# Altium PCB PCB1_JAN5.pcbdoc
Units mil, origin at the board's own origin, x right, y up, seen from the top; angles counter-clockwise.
Board outline 1410 x 855 mil, 2 copper layers (Top Layer, Bottom Layer); 71 components, 53 nets, 261 pads, 16 vias.
Unrouted connection lines stored in the file: 119.
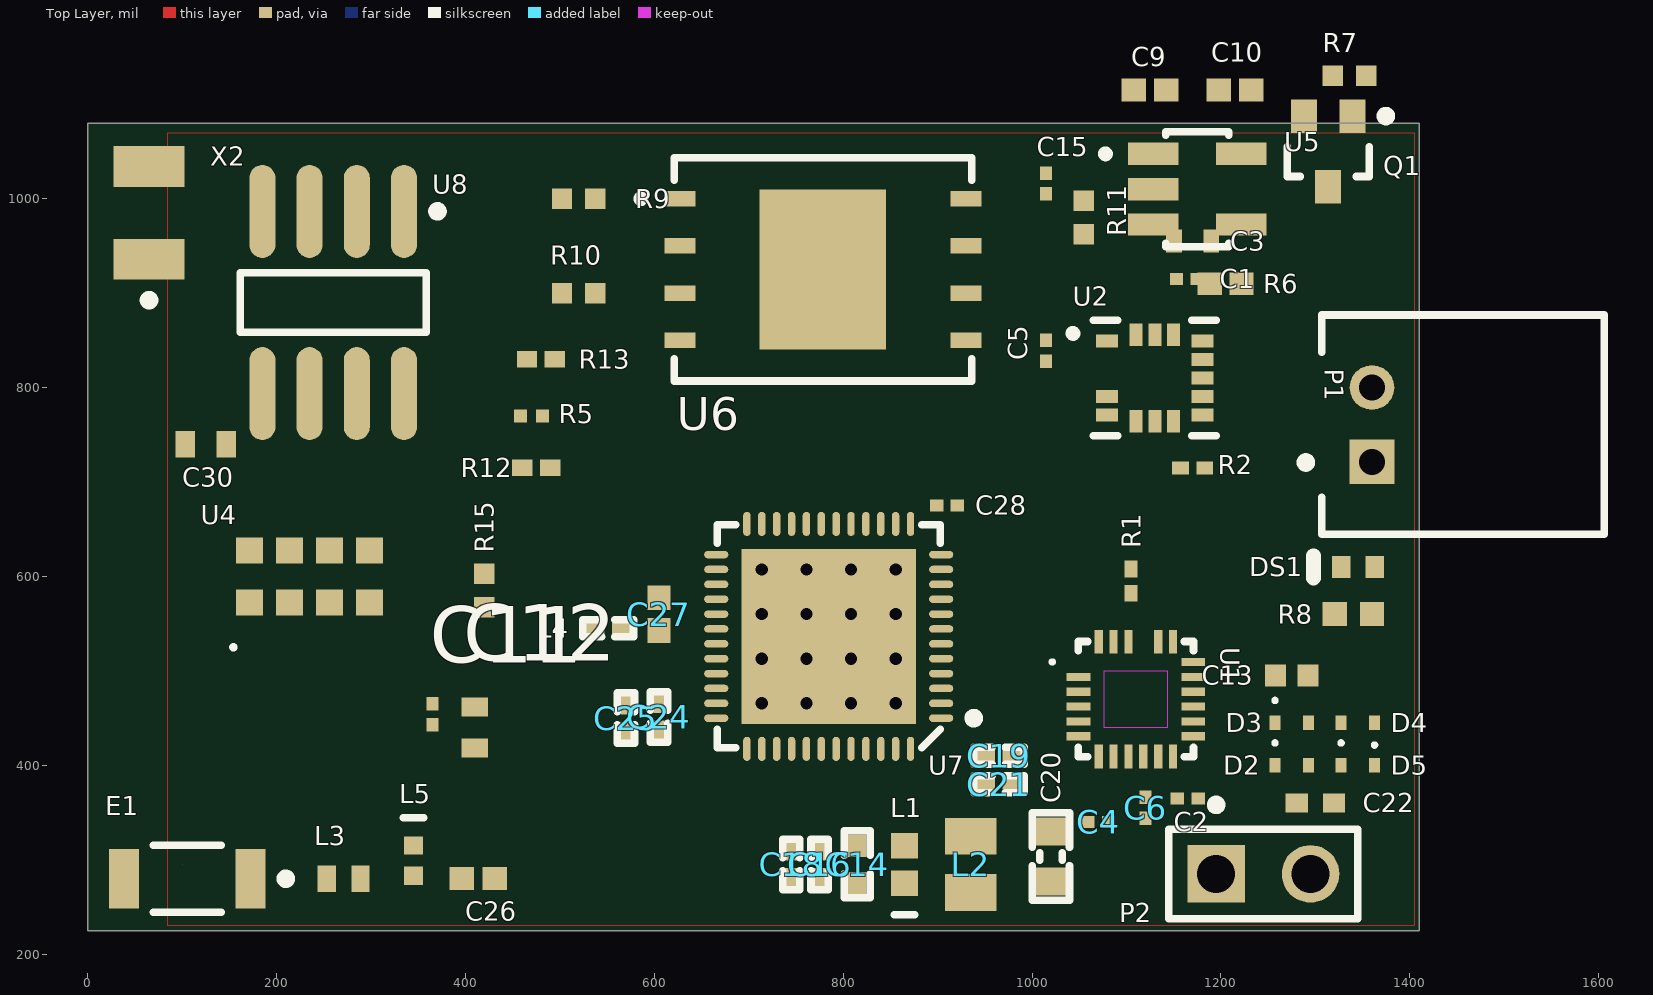
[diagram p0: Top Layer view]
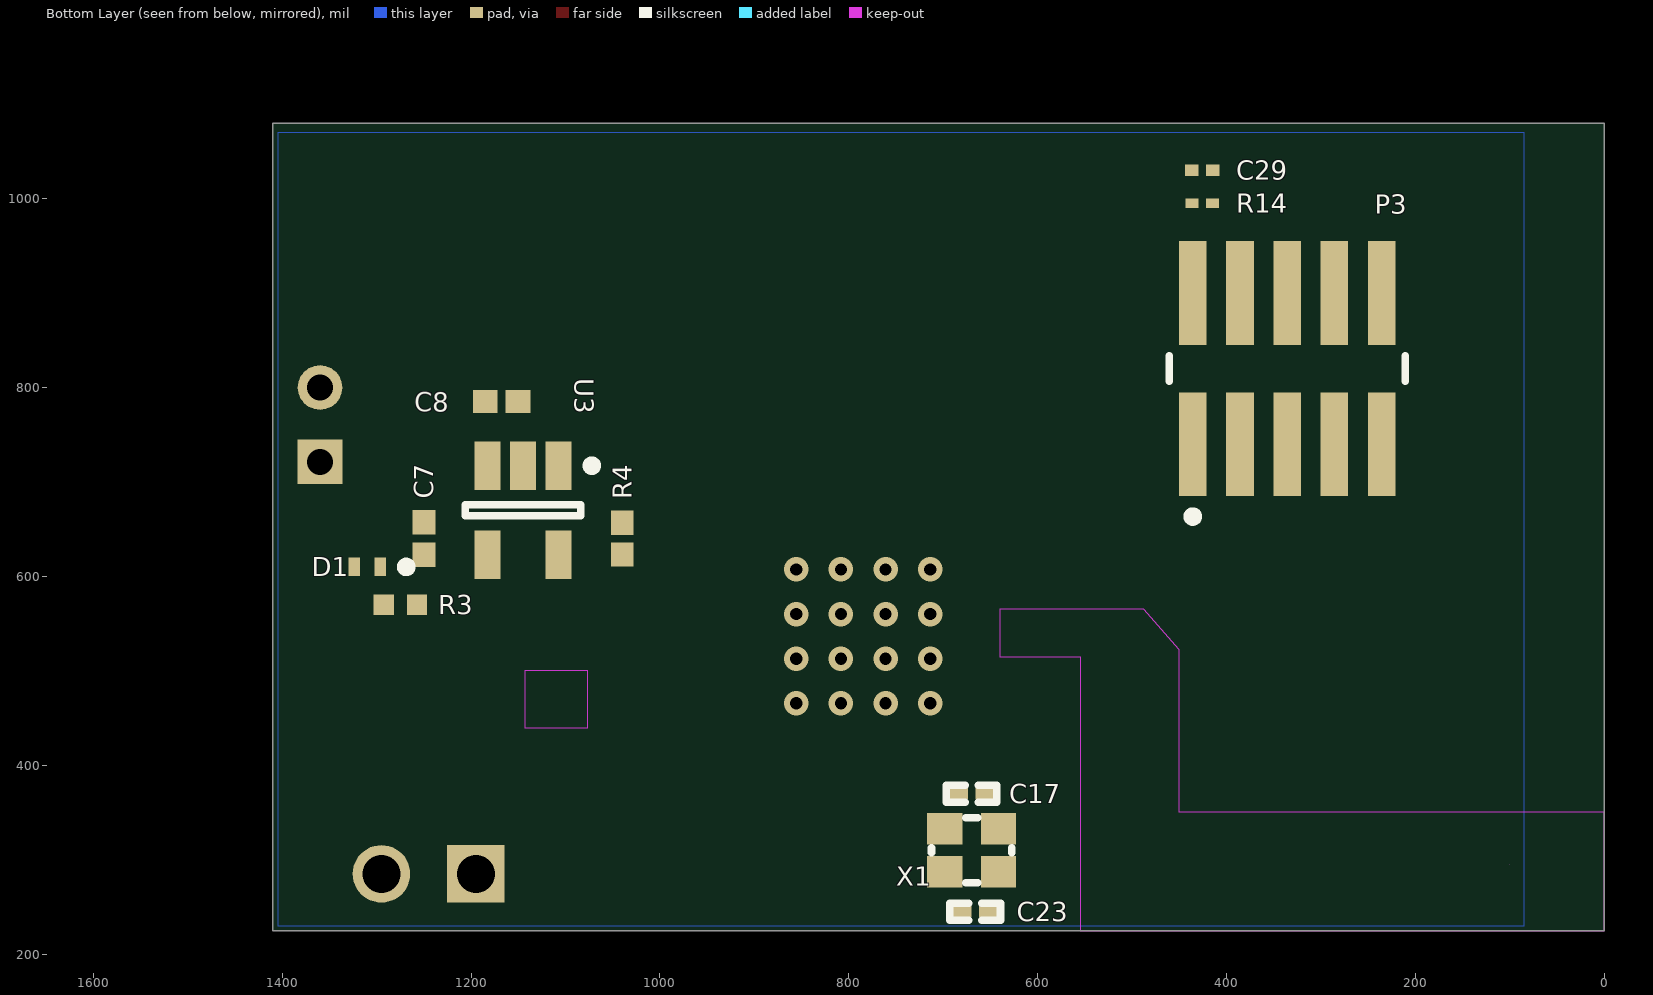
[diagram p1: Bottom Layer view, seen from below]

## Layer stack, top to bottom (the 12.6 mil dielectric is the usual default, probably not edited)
Top Solder: solder mask 0.4, Solder Resist, Dk 3.5
Top Layer: signal copper 1.4
Dielectric 1: dielectric 12.6, FR-4, Dk 4.8
Bottom Layer: signal copper 1.4
Bottom Solder: solder mask 0.4, Solder Resist, Dk 3.5

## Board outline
1410,225 1410,1080 0,1080 0,225
cut-out: 100,295

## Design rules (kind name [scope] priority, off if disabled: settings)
Clearance CPWG [InNet('RF')] p1: gap=5 ignorepadtopadclearanceinfootprint=TRUE // RF
Clearance [All] p2: gap=5 ignorepadtopadclearanceinfootprint=TRUE except(10: Via-Via)
HoleSize [All] p1: absolutevalues=TRUE maxlimit=100 minlimit=0.6 maxpercent=80.000 minpercent=20.000
MinimumSolderMaskSliver [All] p1: minsoldermaskwidth=5
PolygonConnect PolygonConnect_5 [All vs IsNamedPolygon('Top Layer-GND')] p1: thpad.connectstyle=Relief thpad.reliefconductorwidth=10 thpad.reliefentries=4 thpad.polygonreliefangle="90 Angle" thpad.airgapwidth=10 smdpad.connectstyle=Direct smdpad.reliefconductorwidth=10 smdpad.reliefentries=4 smdpad.polygonreliefangle="90 Angle" smdpad.airgapwidth=10 via.connectstyle=Direct via.reliefconductorwidth=10 via.reliefentries=4 via.polygonreliefangle="90 Angle" via.airgapwidth=10
PolygonConnect PolygonConnect_4 [All vs IsNamedPolygon('Bottom Layer-GND')] p2: thpad.connectstyle=Relief thpad.reliefconductorwidth=10 thpad.reliefentries=4 thpad.polygonreliefangle="90 Angle" thpad.airgapwidth=10 smdpad.connectstyle=Direct smdpad.reliefconductorwidth=10 smdpad.reliefentries=4 smdpad.polygonreliefangle="90 Angle" smdpad.airgapwidth=10 via.connectstyle=Direct via.reliefconductorwidth=10 via.reliefentries=4 via.polygonreliefangle="90 Angle" via.airgapwidth=10
PolygonConnect PolygonConnect_3 [All vs IsNamedPolygon('Top Layer-GND')] p3: thpad.connectstyle=Relief thpad.reliefconductorwidth=10 thpad.reliefentries=4 thpad.polygonreliefangle="90 Angle" thpad.airgapwidth=10 smdpad.connectstyle=Relief smdpad.reliefconductorwidth=10 smdpad.reliefentries=4 smdpad.polygonreliefangle="90 Angle" smdpad.airgapwidth=10 via.connectstyle=Direct via.reliefconductorwidth=10 via.reliefentries=4 via.polygonreliefangle="90 Angle" via.airgapwidth=10
PolygonConnect PolygonConnect_2 [All vs IsNamedPolygon('Bottom Layer-GND')] p4: thpad.connectstyle=Relief thpad.reliefconductorwidth=10 thpad.reliefentries=4 thpad.polygonreliefangle="90 Angle" thpad.airgapwidth=10 smdpad.connectstyle=Direct smdpad.reliefconductorwidth=10 smdpad.reliefentries=4 smdpad.polygonreliefangle="90 Angle" smdpad.airgapwidth=10 via.connectstyle=Relief via.reliefconductorwidth=10 via.reliefentries=4 via.polygonreliefangle="90 Angle" via.airgapwidth=10
PolygonConnect PolygonConnect_1 [All vs IsNamedPolygon('Top Layer-GND')] p5: thpad.connectstyle=Relief thpad.reliefconductorwidth=10 thpad.reliefentries=4 thpad.polygonreliefangle="90 Angle" thpad.airgapwidth=10 smdpad.connectstyle=Direct smdpad.reliefconductorwidth=10 smdpad.reliefentries=4 smdpad.polygonreliefangle="90 Angle" smdpad.airgapwidth=10 via.connectstyle=Relief via.reliefconductorwidth=10 via.reliefentries=4 via.polygonreliefangle="90 Angle" via.airgapwidth=10
PolygonConnect [All] p6: connectstyle=Relief reliefconductorwidth=10 reliefentries=4 polygonreliefangle="90 Angle" airgapwidth=10
RoutingVias [All] p1: holewidth=12 width=24 viastyle="Through Hole" minholewidth=12 minwidth=24 maxholewidth=12 maxwidth=24
SilkToSilkClearance [All] p1: silktosilkclearance=7
SilkToSolderMaskClearance [IsPad] p1: minsilkscreentomaskgap=5 clearancetoexposedcopper=TRUE
SolderMaskExpansion [All] p1: expansion=4
Width RF2 [InNet('NetE1_1')] p1: maxlimit=35 minlimit=35 preferedwidth=35 minimp=50.000000 maximp=50.000000 favimp=50.000000
Width RF1 [InNet('NetC26_1')] p2: maxlimit=35 minlimit=35 preferedwidth=35 minimp=50.000000 maximp=50.000000 favimp=50.000000
Width RF [InNet('RF')] p3: maxlimit=35 minlimit=35 preferedwidth=35 minimp=50.000000 maximp=50.000000 favimp=50.000000
Width [All] p4: maxlimit=8 minlimit=8 preferedwidth=8 minimp=50.000000 maximp=50.000000 favimp=50.000000
26 further rules are at their usual default settings.

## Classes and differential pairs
component class "SimPL_IMU_v1_1 _JAN5": C14 C15 C16 C17 C18 C19 C20 C21 C23 C24 C25 C26 C27 C28 C29 C30 E1 L1 L2 L3 L4 L5 P3 R9 R10 R11 R12 R13 R14 R15 U6 U7 U8 X1 X2
component class SimPL_IMU_v1_0_JAN5: C1 C2 C3 C4 C5 C6 C7 C8 C9 C10 C11 C12 C13 C22 D1 D2 D3 D4 D5 DS1 P1 P2 Q1 R1 R2 R3 R4 R5 R6 R7 R8 U1 U2 U3 U4 U5

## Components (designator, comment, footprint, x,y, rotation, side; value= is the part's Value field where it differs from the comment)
C1 "0.1uF" CAPC0603X33X15LL03T05 1163.98,915 r180 top
C2 "0.1uF" CAPC0603X33X15LL03T05 1165,365 r0 top
C3 "1.0uF" CAPC1005X70X10LL20T00 1170,955 r180 top
C4 "0.1uF" CAPC0603X33X15LL03T05 1070,340 r0 top
C5 "0.1uF" CAPC0603X33X15LL03T05 1015,838.98 r90 top
C6 "0.1uF" CAPC0603X33X15LL03T05 1120,355 r90 top
C7 "4.7uF" CAPC1005X55X25NL05T10 1250,640 r270 bottom
C8 "4.7uF" CAPC1005X55X25NL05T10 1167.68,785 r0 bottom
C9 "1uF" CAPC1005X55X25NL05T10 1125,1115 r0 top
C10 "1uF" CAPC1005X55X25NL05T10 1215,1115 r0 top
C11 "0.1uF" CAPC0603X33X15LL03T05 365,453.98 r90 top
C12 "TACK225M006QTA" CAPC1005X70X10NL20T00 410,440 r90 top
C13 "CL05A226MQ5QUNC" *CAPC1005X55N 1275,495 r180 top
C14 "1.0µF" CAPC1005X04L 815,295 r90 top
C15 "0.1uF" CAPC0603X33X15LL03T05 1015,1016.02 r270 top
C16 "12pF" CAPC0603X03L 775,295 r90 top
C17 "12pF" CAPC0603X03L 670,370 r180 bottom
C18 "12pF" CAPC0603X03L 745,295 r90 top
C19 "100nF" CAPC0603X03L 965,410 r0 top
C20 "4.7µF" CAPC1608X06L 1020,303.43 r270 top
C21 "100nF" CAPC0603X03L 965,380 r0 top
C22 "6.8nF" 0402 1300,360 r180 top
C23 "12pF" CAPC0603X03L 666.22,245 r0 bottom
C24 "100pF" CAPC0603X03L 605,451.22 r270 top
C25 "100pF" CAPC0603X03L 570,450 r90 top
C26 "1.0pF" CAPC1005X55X25NL05T10 413.58,279.96 r0 top
C27 "1.0pF" CAPC1005X55X25NL05T10 605,560 r270 top
C28 "0.1uF" CAPC0603X33X15LL03T05 910,675 r180 top
C29 "02016D104KAT2A" CAPC0603X33X15LL03T05 425.83,1030 r180 bottom
C30 "TACK225M006QTA" CAPC1005X70X10NL20T00 125,740 r0 top
D1 "LNJ247W82RA" PNSC-CHIP-2_V 1310,610 r180 bottom
D2 "NSR0140P2T5G" ONSC-SOD-923-2-514AA-01_D_V 1275,400 r0 top
D3 "NSR0140P2T5G" ONSC-SOD-923-2-514AA-01_D_V 1275,445 r0 top
D4 "NSR0140P2T5G" ONSC-SOD-923-2-514AA-01_D_V 1345,445 r180 top
D5 "NSR0140P2T5G" ONSC-SOD-923-2-514AA-01_D_V 1345,400 r0 top
DS1 "SML-P11MTT86" ROHM-SML-P11MT_V 1345.24,610 r180 top
E1 "2450AT18A100E" JT-2450AT18A100-2_V 105.51,279.81 r180 top
L1 "15nH" INDC1005X55X25ML05T10_A 865,295 r90 top
L2 "10uH" MURA-IND0805_L 935,295 r270 top
L3 "3.9nH" *INDC1006X60N 271.09,279.81 r180 top
L4 "3.3nH" INDC0603X03L 551.22,545 r180 top
L5 "2.7nH" INDC1005X55X25LL05T10_A 345,299.06 r270 top
P1 "Battery Header" JST-S2B-PH-K-S_V 1456.46,760.63 r90 top
P2 "2pin header" AMPH-68000-102HLF_V 1245,285 r0 top
P3 "FTSH-105-01-L-DV-K-TR" SMTC-FTSH-105-01-L-DV-K_V 335.83,820 r180 bottom
Q1 "BSS138W-7-F" DIOD-SOT323-3_V 1313.62,1050 r270 top
R1 "10k" RESC0603X26X15NL03T05 1105,595 r90 top
R2 "10k" RESC0603X26X15NL03T05 1170,715 r0 top
R3 "330" RESC1005X40X25NL05T05 1275,570 r180 bottom
R4 "2.2K" RESC1005X40X25NL10T10 1040,640 r270 bottom
R5 "8.2k" RESC0201(0603)_L 470,770 r0 top value="8200.00 Ohm"
R6 "2.2k" RESC1005X40X25NL10T10 1205,910 r0 top
R7 "CRCW04022K20FKED" RESC1005X40X25NL05T05 1336.34,1130 r0 top
R8 "ERJ2RKF3300X" RESC1005X40X25ML05T05 1340.32,560 r180 top
R9 "10k" RESC1005X40X25NL05T05 520,1000 r180 top
R10 "10k" RESC1005X40X25NL05T05 520,900 r180 top
R11 "10k" RESC1005X40X25NL05T05 1055,980 r90 top
R12 "2.2K" RESC0603X28X15ML05T05 475,715 r0 top
R13 "2.2K" RESC0603X28X15ML05T05 480,830 r0 top
R14 "ERJ-1GEJ104C" RESC0603X26X15LL03T05 425.83,995 r0 bottom
R15 "1k" RESC1005X40X25NL05T05 420,585 r90 top
U1 "ICM-20649" *QFN40P300X300X95-24N 1110,470 r0 top
U2 "ADXL372BCCZ-RL7" *PQFN50P322X300X114-16N 1130,810 r0 top
U3 "MCP73831T-2ATI/OT" SOT-23-OT5_M 1145,670 r270 bottom
U4 "VCNL4040M3OE" *VISHAY_VCNL4040_4X2X1.1 235,600 r90 top
U5 "AP2112K-3.3TRG1" *SOT95P285X140-5N 1175,1010 r0 top
U6 "MT25QL256ABA1EW9-0SIT" *SON127P600X800X80-9N 778.62,925 r0 top
U7 "nRF52832-QFAA" QFN40P600X600X90-48N 784.73,536.46 r180 top
U8 "DS1388Z-33+T&R" S8+4_M 260,890 r270 top
X1 "32MHz" BT-XTAL_2016 670,310 r180 bottom
X2 "32.768KHz-T" ABRA-ABS07-2_V 65,985 r90 top

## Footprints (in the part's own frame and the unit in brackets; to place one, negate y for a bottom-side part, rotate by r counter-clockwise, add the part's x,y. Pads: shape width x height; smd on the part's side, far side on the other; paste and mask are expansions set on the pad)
0402 [mm] "Chip Capacitor, Body 1.0x0.5mm, IPC High Density"
  rect 0.6x0.5 smd: 1(-0.5,0) 2(0.5,0)
  body extent -0.55,-0.3 0.55,0.3, height 1.3
*CAPC1005X55N [mm]
  rect 0.56x0.6 smd: 1(-0.435,0) 2(0.435,0)
*INDC1006X60N [mm]
  rect 0.49x0.7 smd: 1(-0.453,0) 2(0.453,0)
*PQFN50P322X300X114-16N [mm]
  rect 0.6x0.35 smd: 1(-1.285,1) 4(-1.285,-0.5) 5(-1.285,-1) 9(1.285,-1) 10(1.285,-0.5) 11(1.285,0) 12(1.285,0.5) 13(1.285,1)
  rect 0.6x0.35 on Top Overlay: 2(-1.285,0.5) 3(-1.285,0)
  rect 0.35x0.6 smd: 6(-0.5,-1.165) 7(0,-1.165) 8(0.5,-1.165) 14(0.5,1.165) 15(0,1.165) 16(-0.5,1.165)
  silkscreen extent -2.3,-1.55 1.65,1.55
*QFN40P300X300X95-24N [mm]
  rect 0.64x0.22 on Top Overlay: 1(-1.545,1)
  rect 0.64x0.22 smd: 2(-1.545,0.6) 3(-1.545,0.2) 4(-1.545,-0.2) 5(-1.545,-0.6) 6(-1.545,-1) 13(1.545,-1) 14(1.545,-0.6) 15(1.545,-0.2) 16(1.545,0.2) 17(1.545,0.6) 18(1.545,1)
  rect 0.22x0.64 smd: 7(-1,-1.545) 8(-0.6,-1.545) 9(-0.2,-1.545) 10(0.2,-1.545) 11(0.6,-1.545) 12(1,-1.545) 19(1,1.545) 20(0.6,1.545) 22(-0.2,1.545) 23(-0.6,1.545) 24(-1,1.545)
  rect 0.22x0.64 on Top Overlay: 21(0.2,1.545)
  Keep-Out Layer region: -0.85,0.77 0.85,0.77 0.85,-0.77 -0.85,-0.77
  Keep-Out Layer region: -0.85,0.77 0.85,0.77 0.85,-0.77 -0.85,-0.77
  Keep-Out Layer region: -0.85,0.77 0.85,0.77 0.85,-0.77 -0.85,-0.77
  Keep-Out Layer region: -0.85,0.77 0.85,0.77 0.85,-0.77 -0.85,-0.77
  Keep-Out Layer region: -0.85,0.77 0.85,0.77 0.85,-0.77 -0.85,-0.77
  Keep-Out Layer region: -0.85,0.77 0.85,0.77 0.85,-0.77 -0.85,-0.77
  silkscreen extent -2.3,-1.55 1.55,1.55
*SON127P600X800X80-9N [mm]
  rect 0.84x0.42 smd: 1(-3.845,1.905) 2(-3.845,0.635) 3(-3.845,-0.635) 4(-3.845,-1.905) 5(3.845,-1.905) 6(3.845,-0.635) 7(3.845,0.635) 8(3.845,1.905)
  rect 3.4x4.3 smd: 9(0,0)
  silkscreen extent -4.99,-3 4,3
*SOT95P285X140-5N [mm]
  rect 1.35x0.6 smd: 1(-1.185,0.95) 2(-1.185,0) 3(-1.185,-0.95) 4(1.185,-0.95) 5(1.185,0.95)
  silkscreen extent -2.57,-1.55 0.85,1.55
*VISHAY_VCNL4040_4X2X1.1 [mm]
  rect 0.7x0.725 smd: 1(-0.7,1.612) 2(-0.7,0.538) 3(-0.7,-0.537) 4(-0.7,-1.612) 5(0.7,-1.612) 6(0.7,-0.537) 7(0.7,0.538) 8(0.7,1.612)
  silkscreen extent -1.96,2 -1.86,2.1
ABRA-ABS07-2_V [mm] "Hand Drawn, 2-Leads, Body 3.2x1.5mm, Pitch 2.5mm"
  rect 1.1x1.9 smd: 1(-1.25,0) 2(1.25,0)
  silkscreen extent -2.47,-0.13 -2.23,0.12, body extent -1.6,-0.75 1.6,0.75, height 0.9
AMPH-68000-102HLF_V [mm] "THD, 2-Leads, Body 5.08x2.41mm, Pitch 2.54mm"
  rect 1.55x1.55 hole 1.02: 1(-1.27,0)
  round 1.55 hole 1.02: 2(1.27,0)
  silkscreen extent -2.54,-1.2 2.54,1.98, body extent -2.54,-1.2 2.54,1.2, height 8.38
BT-XTAL_2016 [mm]
  rect 0.95x0.85 smd: 1(-0.725,-0.575) 2(0.725,-0.575) 3(0.725,0.575) 4(-0.725,0.575)
  silkscreen extent -1.08,-0.88 1.08,0.88, body extent -1.05,-0.85 1.05,0.85, height 0.56
CAPC0603X03L [mm]
  rect 0.5x0.3 smd: 1(-0.35,0) 2(0.35,0)
  silkscreen extent -0.68,-0.23 0.68,0.23, body extent -0.3,-0.15 0.3,0.15, height 0.3
CAPC0603X33X15LL03T05 [mm] "Chip Capacitor, 2-Leads, Body 0.60x0.30mm, IPC High Density"
  rect 0.36x0.32 smd: 1(-0.28,0) 2(0.28,0)
  body extent -0.32,-0.17 0.32,0.17, height 0.33
CAPC1005X04L [mm]
  rect 0.6x0.5 smd: 1(-0.5,0) 2(0.5,0)
  silkscreen extent -0.9,-0.35 0.9,0.35, body extent -0.51,-0.25 0.51,0.25, height 0.5
CAPC1005X55X25NL05T10 [mm] "Chip Capacitor, 2-Leads, Body 1.00x0.50mm, IPC Medium Density"
  rect 0.66x0.62 smd: 1(-0.44,0) 2(0.44,0)
  body extent -0.53,-0.28 0.53,0.27, height 0.55
CAPC1005X70X10LL20T00 [mm] "Chip Capacitor, 2-Leads, Body 1.00x0.50mm, IPC High Density"
  rect 0.42x0.62 smd: 1(-0.5,0) 2(0.5,0)
  body extent -0.6,-0.35 0.6,0.35, height 0.7
CAPC1005X70X10NL20T00 [mm] "Chip Capacitor, 2-Leads, Body 1.00x0.50mm, IPC Medium Density"
  rect 0.52x0.72 smd: 1(-0.55,0) 2(0.55,0)
  body extent -0.6,-0.35 0.6,0.35, height 0.7
CAPC1608X06L [mm]
  rect 0.75x0.8 smd: 1(-0.675,0) 2(0.675,0)
  silkscreen extent -1.17,-0.5 1.18,0.5, body extent -0.8,-0.43 0.8,0.43, height 0.8
DIOD-SOT323-3_V [mm] "SOT323, 3-Leads, Body 2.2x1.35mm, Pitch 0.65mm"
  rect 0.9x0.7 smd: 1(-0.95,0.65) 2(-0.95,-0.65) 3(0.95,0)
  silkscreen extent -1.07,-1.1 0.67,1.68, body extent -1.1,-1.1 1.1,1.1, height 1.07
INDC0603X03L [mm]
  rect 0.5x0.3 smd: 1(-0.35,0) 2(0.35,0)
  silkscreen extent -0.68,-0.23 0.68,0.23, body extent -0.31,-0.16 0.31,0.16, height 0.26
INDC1005X55X25LL05T10_A [mm] "Chip Inductor, 2-Leads, Body 1.05x0.55mm, IPC High Density"
  rect 0.49x0.52 smd: 1(-0.405,0) 2(0.405,0)
  silkscreen extent -1.15,-0.27 -1.15,0.27, body extent -0.52,-0.28 0.53,0.28, height 0.55
INDC1005X55X25ML05T10_A [mm] "Chip Inductor, 2-Leads, Body 1.05x0.55mm, IPC Low Density"
  rect 0.69x0.72 smd: 1(-0.505,0) 2(0.505,0)
  silkscreen extent -1.35,-0.27 -1.35,0.27, body extent -0.52,-0.28 0.53,0.28, height 0.55
JST-S2B-PH-K-S_V [mm] "THD, 2-Leads, Body 7.6x5.9mm, Pitch 2mm"
  rect 1.2x1.2 hole 0.7: 1(-1,2.45)
  round 1.2 hole 0.7: 2(1,2.45)
  silkscreen extent -2.95,-3.8 2.95,4.35, body extent -2.95,-3.8 2.95,3.8, height 4.8
JT-2450AT18A100-2_V [mm] "Chip Antenna, 2-Leads, Body 3.4x1.8mm"
  rect 0.8x1.6 smd: 1(-1.7,0) 2(1.7,0)
  silkscreen extent -2.78,-0.9 0.91,0.9, body extent -1.7,-0.9 1.7,0.9, height 1.4
MURA-IND0805_L [mm] "Chip Inductor, 2-Leads, Body 2.2x1.45mm, IPC High Density"
  rect 0.99x1.39 smd: 1(-0.755,0) 2(0.755,0)
  body extent -1.1,-0.72 1.1,0.72, height 1.45
ONSC-SOD-923-2-514AA-01_D_V [mm] "SOD, 2-Leads, Body 0.8x0.6mm"
  rect 0.3x0.4 smd: 1(-0.45,0) 2(0.45,0)
  silkscreen extent -0.5,0.55 -0.4,0.65, body extent -0.4,-0.3 0.4,0.3, height 0.43
PNSC-CHIP-2_V [mm] "CHIP, 2-Leads, Body 1x0.5mm, Pitch 0.7mm"
  rect 0.3x0.5 smd: 1(0.35,0) 2(-0.35,0)
  silkscreen extent 0.92,-0.12 1.17,0.12, body extent -0.5,-0.25 0.5,0.25, height 0.25
QFN40P600X600X90-48N [mm]
  oval 0.65x0.2 smd: 1(-3.025,2.2) 2(-3.025,1.8) 3(-3.025,1.4) 4(-3.025,1) 5(-3.025,0.6) 6(-3.025,0.2) 7(-3.025,-0.2) 8(-3.025,-0.6) 9(-3.025,-1) 10(-3.025,-1.4) 11(-3.025,-1.8) 12(-3.025,-2.2) 25(3.025,-2.2) 26(3.025,-1.8) 27(3.025,-1.4) 28(3.025,-1) 29(3.025,-0.6) 30(3.025,-0.2) 31(3.025,0.2) 32(3.025,0.6) 33(3.025,1) 34(3.025,1.4) 35(3.025,1.8) 36(3.025,2.2)
  oval 0.2x0.65 smd: 13(-2.2,-3.025) 14(-1.8,-3.025) 15(-1.4,-3.025) 16(-1,-3.025) 17(-0.6,-3.025) 18(-0.2,-3.025) 19(0.2,-3.025) 20(0.6,-3.025) 21(1,-3.025) 22(1.4,-3.025) 23(1.8,-3.025) 24(2.2,-3.025) 37(2.2,3.025) 38(1.8,3.025) 39(1.4,3.025) 40(1,3.025) 41(0.6,3.025) 42(0.2,3.025) 43(-0.2,3.025) 44(-0.6,3.025) 45(-1,3.025) 46(-1.4,3.025) 47(-1.8,3.025) 48(-2.2,3.025)
  rect 4.7x4.7 smd: 49(0,0)
  silkscreen extent -4.03,-3 3,3, body extent -3.02,-3.02 3.02,3.02, height 0.86
RESC0201(0603)_L [mm] "Chip Resistor, Body 0.6x0.3mm, IPC High Density"
  rect 0.35x0.35 smd: 1(-0.3,0) 2(0.3,0)
  body extent -0.31,-0.16 0.31,0.16, height 0.3
RESC0603X26X15LL03T05 [mm] "Chip Resistor, 2-Leads, Body 0.60x0.30mm, IPC High Density"
  rect 0.35x0.25 smd: 1(-0.275,0) 2(0.275,0)
  body extent -0.32,-0.16 0.31,0.17, height 0.26
RESC0603X26X15NL03T05 [mm] "Chip Resistor, 2-Leads, Body 0.60x0.30mm, IPC Medium Density"
  rect 0.45x0.35 smd: 1(-0.325,0) 2(0.325,0)
  body extent -0.32,-0.16 0.32,0.17, height 0.26
RESC0603X28X15ML05T05 [mm] "Chip Resistor, 2-Leads, Body 0.60x0.30mm, IPC Low Density"
  rect 0.55x0.45 smd: 1(-0.375,0) 2(0.375,0)
  body extent -0.33,-0.17 0.33,0.18, height 0.28
RESC1005X40X25ML05T05 [mm] "Chip Resistor, 2-Leads, Body 1.00x0.50mm, IPC Low Density"
  rect 0.65x0.65 smd: 1(-0.5,0) 2(0.5,0)
  body extent -0.53,-0.27 0.53,0.28, height 0.4
RESC1005X40X25NL05T05 [mm] "Chip Resistor, 2-Leads, Body 1.00x0.50mm, IPC Medium Density"
  rect 0.55x0.55 smd: 1(-0.45,0) 2(0.45,0)
  body extent -0.53,-0.27 0.53,0.28, height 0.4
RESC1005X40X25NL10T10 [mm] "Chip Resistor, 2-Leads, Body 1.00x0.50mm, IPC Medium Density"
  rect 0.65x0.6 smd: 1(-0.425,0) 2(0.425,0)
  body extent -0.55,-0.3 0.55,0.3, height 0.4
ROHM-SML-P11MT_V [mm] "SMD, 2-Leads, Body 0.6x1mm"
  rect 0.5x0.6 smd: 1(-0.45,0) 2(0.45,0)
  silkscreen extent 1.2,-0.3 1.2,0.3, body extent -0.5,-0.3 0.5,0.3, height 0.25
S8+4_M [mm] "SOIC, 8-Leads, Body 4.9x3.9mm, Pitch 1.27mm, IPC Low Density"
  oval 2.5x0.7 smd: 1(-2.45,1.905) 2(-2.45,0.635) 3(-2.45,-0.635) 4(-2.45,-1.905) 5(2.45,-1.905) 6(2.45,-0.635) 7(2.45,0.635) 8(2.45,1.905)
  silkscreen extent -2.57,-2.5 0.8,2.93, body extent -2,-2.5 2,2.5, height 1.75
SMTC-FTSH-105-01-L-DV-K_V [mm] "CONN, 10-Leads, Body 6.35x3.43mm, Pitch 1.27mm"
  rect 0.74x2.79 smd: 1(-2.54,-2.035) 2(-2.54,2.035) 3(-1.27,-2.035) 4(-1.27,2.035) 5(0,-2.035) 6(0,2.035) 7(1.27,-2.035) 8(1.27,2.035) 9(2.54,-2.035) 10(2.54,2.035)
  silkscreen extent -3.17,-4.1 3.18,0.34, body extent -3.17,-2.92 3.18,2.92, height 6.12
SOT-23-OT5_M [mm] "SOT23, 5-Leads, Body 2.9x1.7mm, Pitch 0.95mm, Lead Span 2.8mm, IPC Low Density"
  rect 1.3x0.7 smd: 1(-1.2,0.95) 2(-1.2,0) 3(-1.2,-0.95) 4(1.2,-0.95) 5(1.2,0.95)
  silkscreen extent -1.32,-1.55 0.15,1.97, body extent -0.9,-1.55 0.9,1.55, height 1.45

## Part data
C1 C2 C4 C5 C6 C11 C15 C28: library part CMP-2010-01264-1, Manufacturer=Murata, Part Number=GRM033R61A104KE15D
C3: library part CMP-2008-00066-1, Manufacturer="AVX Interconnect / Elco", Part Number=TACK105M010QTA
C7 C8: library part CMP-2008-04549-1, Manufacturer=Murata, Part Number=GRM155R60J475ME47D
C9 C10: library part CMP-2008-04556-1, Manufacturer=Murata, Part Number=GRM155R61A105KE15D
C12 C30: library part CMP-2008-00070-1, Manufacturer="AVX Interconnect / Elco"
C13: Capacitance=22uF, Package size=0402
C14: library part C0402-1µ0, "Capacitor, X5R, ±5%", Part Number=C0402C105K9PACTU
C16: library part C0201-12p, "Capacitor, NP0, ±2%", Part Number=CC0201JRNPO8BN120
C17 C18 C23: library part C0201-12p, "Capacitor, NP0, ±2%", Manufacturer Part Number=CC0201JRNPO8BN120
C19 C21: library part C0201-100n, "Capacitor, X7R, ±10%", Manufacturer Part Number=CC0201KRX5R5BB104
C20: library part C0603-4µ7, "Capacitor, X5R, ±10%", Manufacturer Part Number=C0603C475K9PACTU
C22: library part 0.1UF-0402-16V-10%, "0.1µF ceramic capacitors    A capacitor is a passive two-terminal electrical component used to store electrical energy temporarily in an electric field.", Part Number=CC0402KRX7R9BB682
C24 C25: library part C0201-100p, "Capacitor, NP0, ±5%", Manufacturer Part Number=CC0201JRNPO9BN101
C26 C27: library part CMP-2008-03808-1, Manufacturer=Murata, Part Number=GJM1555C1H1R0BB01D
C29: library part CMP-2010-00159-1, Manufacturer="AVX Interconnect / Elco"
D1: library part CMP-0456-00001-2, "Hight Bright Surface Mounting Chip LED (Red), 55 mW, -30 to 85 degC, 1.0 x 0.5 x 0.2 mm  SMD", Forward Voltage="1.95 V", Manufacturer=Panasonic, Reverse Current="100 uA"
D2 D3 D4 D5: library part CMP-1055-00493-1, "Schottky Barrier Diode, 2-Pin SOD-923, Pb-Free, Tape and Reel", Manufacturer="On Semiconductor"
DS1: library part CMP-2000-07126-1, "LED Green, 54 mW, 20 mA, -40 to 85 degC, 2-Pin SMD, RoHS, Tape and Reel", Color=Green, Forward (Drive) Current=20mA, Forward Voltage=1.9V, Manufacturer="Lite-On Inc.", Manufacturer Part Number=LTST-C170KGKT, Package Description="2-Pin Surface Mount Device, Body 0.6 x 1 mm", Package Reference=SML-P11MT
E1: library part CMP-2000-05167-1, "Ceramic Antenna, 2.45 GHZ, 2 W, -40 to 125 degC, 2-Pin SMD, RoHS, Tape and Reel", Manufacturer="Johanson Technology", Maximum Frequency=2500MHz, Minimum Frequency=2400MHz, Package=2Case18-4
L1: library part CMP-2100-03652-1, "Chip Inductor, 15 nH, +/- 5%, 100 MHz, -55 to 125 degC, 0402 (1005 Metric), RoHS, Paper Tape", Case/Package=0402, Case Code (Metric)=1005, Current Rating=300mA, DC Resistance (DCR)=320mOhm, Inductance=15nh, Manufacturer=Murata, Manufacturer Part Number=HK100515NJ-T, Max Operating Temperature=125degC, Min Operating Temperature=-55degC, Package Description="2-Pin Surface Mount Device, Body 1 x 0.5 mm", Package Quantity=10000, Self Resonant Frequency=2.5GHz, Test Frequency=100MHz, Tolerance=5%
L2: library part CMP-2000-06587-1, "Fixed Inductor, 10 uH, +/-20%, -55 to 125 degC, 2-Pin SMD (0805), RoHS, Tape and Reel", Case Size/Dimension=0805, DC Resistance=0.6, Inductance-Nom=10H, Manufacturer=Bourns, Manufacturer Part Number=CV201210-100K, Package Description="2-Pin Surface Mount Device, Body 2 x 1.25 mm", Package Reference=IND0805, Rated Current-Max=100mA, Tolerance (%)=20%
L3: library part MHQ1005P3N9CT000, "Inductor, 3.9nh, 0.2nh, 0.9a, 0402", Manufacturer Part Number=L-07C3N9SV6T, Package="1006 TDK"
L4: library part L0201-3n3, "High frequency chip inductor ±5%", Manufacturer=Murata, Manufacturer Part Number=LQP03TN3N3B02D
L5: library part CMP-2000-06580-1, "Chip Inductor, 2.7 nH, +/- 0.3 nH, 300 mA, -55 to 125 degC, 0402 (1005 Metric), RoHS, Tape and Reel", Current Rating=300mA, DC Resistance (DCR)=150mOhmMax, Frequency - Self Resonant=6GHz, Frequency - Test=100MHz, Manufacturer=Murata, Manufacturer Part Number=L-07C2N7SV6T, Operating Temperature=-55°C~125°C, Package / Case=0402(1005Metric), Package Description="2-Pin Surface Mount Device, Body 1 x 0.5 mm", Package Reference=0402, Q @ Freq=8@100MHz, Standard Package=10,000, Tolerance=±0.3nH
P1: library part CMP-1755-00004-1, "Male Header, Pitch 2 mm, 1 x 2 Position, Height 4.8 mm, Tail Length 3.4 mm, -25 to 85 degC, RoHS, Bulk", Capacitance="10 uF", Case\Package=Radial, Max Operating Temperature="85 degC", Min Operating Temperature="-40 degC", Package Quantity=200, Tolerance=20%, Voltage Rating="50 V"
P2: library part CMP-2000-05666-1, "Male Header, Pitch 2.54 mm, 1 x 2 Position, Height 8.38 mm, Tail Length 2.41 mm, RoHS, Bulk", Current Rating=3A, Flammability Rating=UL94V-0, Insulation Resistance=5000MOhms, Manufacturer=FCI, Operating Temperature Range=-65Cto+125C, Package Description="Male Header, Pitch 2.54 mm, 1 x 2 Position, Height 8.38 mm, Tail Length 2.41 mm", Package Reference=68000-102HLF, Voltage Rating=1.5kV
P3: library part CMP-2000-06293-1, "Male Header, Pitch 1.27 mm, 2 x 5 Position, Height 6.12 mm, -55 to 125 degC, RoHS, Tape and Reel", Manufacturer=Amphenol, Package Description="Male Header, Pitch 1.27 mm, 2 x 5 Position, Height 5.97 mm, Tail Length 4.32 mm", Package Reference=20021121-00010C4LF
Q1: library part CMP-2000-05968-1, "N-Channel Enhancement Mode Mosfet, 50 V, 200 mA, -55 to 150 degC, 6-Pin SOT-323, RoHS, Tape and Reel", Id - Continuous Drain Current=200mA, Manufacturer=DiodesIncorporated, Maximum Operating Temperature=+150C, Minimum Operating Temperature=-55C, Package / Case=SOT-323-3, Package Description="3-Pin Small Outline Transistor, Body 2 x 1.25 mm, Pitch 0.65 mm", Package Reference=SOT323, Pd - Power Dissipation=200mW, Rds On - Drain-Source Resistance=1.4Ohms, Vds - Drain-Source Breakdown Voltage=75V, Vgs - Gate-Source Voltage=20V
R1 R2: library part CMP-2004-02627-1, Manufacturer=Panasonic, Part Number=ERJ-1GEF1002C
R3: library part CMP-2002-08523-1, Manufacturer="Vishay Dale", Part Number=CRCW0402330RFKED
R4 R6: library part CMP-2002-05881-1, Manufacturer=Panasonic, Part Number=ERA2AEB222X
R5: library part CMP-1010-00519-1, "8K2 0.05W 1% 0201 (0603 Metric)  SMD", Case-EIA=0201, Case-Metric=0603, Manufacturer=Panasonic, Part Number=ERJ-1GNF8201C, Power="0.05 W", Tolerance="1 %"
R7: library part CMP-2002-08452-1, Manufacturer="Vishay Dale"
R8: library part CMP-2002-01143-1, Manufacturer=Panasonic
R9 R10 R11: library part CMP-2002-00607-3, "Chip Resistor, 10 KOhm, +/- 1%, 100 mW, -55 to 155 degC, 0402 (1005 Metric), RoHS, Tape and Reel", Case\/Package=0402, Case Code (Metric)=1005, Manufacturer="Basic Passives", Max Operating Temperature="155 degC", Min Operating Temperature="-55 degC", Package Quantity=10000, PartNumber=ERJ-2RKF1002X, Power Rating="100 mW", Resistance="10 KOhm", Tolerance=1%, Voltage Rating="50 V"
R12 R13: library part CMP-2004-00412-1, Manufacturer="Vishay Dale", Part Number=CRCW02012K20FNED
R14: library part CMP-2004-03147-1, Manufacturer=Panasonic
R15: library part CMP-2002-08276-1, Manufacturer="Vishay Dale", Part Number=CRCW04021K00FKED, Supplier Part Number 1=541-1.00KLDKR-ND
U1: "Wide-Range 6-Axis MEMS MotionTracking Device for Sports and High Impact Applications", Package="QFN-24 InvenSense"
U2: "Accelerometer Triple ±200g 2.5V 16-Pin LGA T/R", Package="LGA-16 Analog Devices"
U3: library part CMP-0133-00144-1, "Miniature Single-Cell, Fully Integrated Li-Ion, Li-Polymer Charge Management Controller, 4.2V, 5-Pin SOT-23, Industrial Temperature, Tape and Reel"
U4: "VCNL4040 Series 3.6 V 200 mm 16 Bit I2C SMT Proximity and Ambient Light Sensor", Package="SMD-8 Vishay"
U5: "AP2112 Series 0.6 A 3.3 V Fixed Output SMT LDO Linear Regulator - SOT23-5", Package="SOT-753 Diodes Inc."
U6: "NOR Flash Serial-SPI 3.3V 256Mbit 256M x 1bit 8-Pin WPDFN", Package="WDFN-8 Micron Technology"
U7: "Multi-protocol Bluetooth Low Energy, ANT and 2.4GHz proprietary system-on-chip", Manufacturer="Nordic Semiconductor"
U8: library part CMP-0254-00385-1, "I2C Real-Time Clock/Supervisor with Trickle Charger and 512 Byte EEPROM, 3.3V, 8-Pin SO, -40 to 85 degC, Pb-Free, Reel"
X1: library part XTAL_SMD2016_32MHz_8pF_Epson, "XTAL SMD 2016, 32MHz, Cl=8pF, Total Tol: ±40ppm", Manufacturer="ECS Inc.", Manufacturer Part Number=ECS-320-8-37B-CKY-TR, Supplier part number=171-2806
X2: library part CMP-0447-00001-2, "Crystal, 32.768 kHz, 12.5 pF, -40 to 85 degC, SMD Low Profile 3.2 x 1.5 x 0.9 mm, Tape and Reel", Equivalent Series Resistance (R1)="70 Kohm", Frequency="32.768 kHz", Frequency Tolerance @+25degC="+/- 20 ppm", Insulation Resistance (Min)="500 Mohm", Load Capacitance (CL)="12.5 pF", Manufacturer=Abracon, Operating Temperature="-40 to 85 degC", PartNumber=ABS07-32.768KHz-T, Q Value (Type)=30000, Shunt Capacitance (C0)="0.9 to 1.2 pF"

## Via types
v1: diameter 25.98, hole 12.99, Top Layer to Bottom Layer, 16 vias

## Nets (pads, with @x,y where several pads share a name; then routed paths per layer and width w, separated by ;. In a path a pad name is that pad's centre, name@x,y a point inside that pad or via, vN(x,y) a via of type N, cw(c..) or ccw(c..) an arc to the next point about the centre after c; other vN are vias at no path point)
+3V3: C1.2 C2.2 C3.2 C4.2 C5.2 C9.2 C11.2 C12.2 C15.2 C20.1 C21.1 C28.2 C29.2 C30.2 P3.1 R1.2 R2.2 R5.2 R8.2 R9.2 R10.2 R11.2 R12.2 R13.2 R14.1 U1.8 U1.13 U2.1 U2.14 U4.3 U4.4 U5.5 U6.8 U7.13 U7.36 U7.48 U8.3 U8.8
ACCEL_CS: R2.1 U2.8 U7.7
ACCEL_MISO: U2.7 U7.8
ACCEL_MOSI: U2.6 U7.9
ACCEL_SCLK: U2.4 U7.10
CATHODE: U4.2 U4.5
COIL1: C22.1 D3.2 D5.1 P2.2
DEC1: C19.1 U7.1
DEC2: C25.2 U7.32
DEC3: C24.1 U7.33
DEC4: C14.2 L1.2 U7.46
GND: C1.1 C2.1 C3.1 C4.1 C5.1 C6.1 C7.1 C8.1 C9.1 C10.1 C11.1 C12.1 C13.1 C14.1 C15.1 C16.1 C17.1 C18.1 C19.2 C20.2 C21.2 C22.2 C23.1 C24.2 C25.1 C27.1 C28.1 C29.1 C30.1 D2.2 D4.1 DS1.2 L5.1 P1.2 P2.1 P3.3 P3.5 Q1.2 R4.1 R15.1 U1.18 U1.20 U2.12 U2.13 U2.16 U3.2 U4.1 U5.2 U6.4 U6.9 U7.31 U7.45 U7.49 U8.4 X1.2 X1.4
GYRO_CS: R1.1 U1.22 U7.6
GYRO_MISO: U1.24 U7.4
GYRO_MOSI: U1.9 U7.3
GYRO_SCLK: U1.23 U7.5
I2C_SCL: R13.1 U4.8 U7.22 U8.6
I2C_SDA: R12.1 U4.7 U7.23 U8.5
IR_INT: R5.1 U4.6 U7.21
MEM_CS: R9.1 U6.1 U7.18
MEM_MISO: U6.5 U7.15
MEM_MOSI: U6.2 U7.19
MEM_SCLK: U6.6 U7.16
MEM_SPI_HOLD: R11.1 U6.7 U7.17
MEM_SPI_W: R10.1 U6.3 U7.20
NetC6_2: C6.2 U1.10
NetC16_2: C16.2 U7.38
NetC18_2: C18.2 U7.37
NetC26_1: C26.1 L3.1 L5.2
NetC27_2: C27.2 L4.1 U7.30
NetD1_1: D1.1 R3.1
NetD1_2: D1.2 U3.1
NetD4_2: D4.2 D5.2
NetDS1_1: DS1.1 R8.1
NetE1_1: E1.1 L3.2
NetL1_1: L1.1 L2.2
NetL2_1: L2.1 U7.47
NetP3_2: P3.2 R14.2 U7.26
NetQ1_1: Q1.1 R7.2
NetQ1_3: Q1.3 R6.1 U5.3
NetR4_2: R4.2 U3.5
NetU8_1: U8.1 X2.2
NetU8_2: U8.2 X2.1
nRESET: P3.10 U7.24
P0.27: U7.39
P0.28/AIN4: U7.40
RF: C26.2 L4.2
RST_CLK: R15.2 U7.27 U8.7
SWDCLK: P3.4 U7.25
VBAT: C8.2 C10.2 P1.1 R6.2 U3.3 U5.1
VBUS: C7.2 C13.2 D2.1 D3.1 R3.2 R7.1 U3.4
XC1: C23.2 U7.34 X1.1
XC2: C17.2 U7.35 X1.3
pads on no net: E1.2 P3.6 P3.7 P3.8 P3.9 U1.1 U1.2 U1.3 U1.4 U1.5 U1.6 U1.7 U1.11 U1.12 U1.14 U1.15 U1.16 U1.17 U1.19 U1.21 U2.2 U2.3 U2.5 U2.9 U2.10 U2.11 U2.15 U5.4 U7.2 U7.11 U7.12 U7.14 U7.28 U7.29 U7.41 U7.42 U7.43 U7.44
copper on no net:
  other v1: 713.87,465.59 761.11,465.59 808.36,465.59 855.6,465.59 713.87,512.84 761.11,512.84 808.36,512.84 855.6,512.84 713.87,560.08 761.11,560.08 808.36,560.08 855.6,560.08 713.87,607.33 761.11,607.33 808.36,607.33 855.6,607.33

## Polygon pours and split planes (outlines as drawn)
GND on Bottom Layer "Bottom Layer-GND" (solid, shelved, pour order 4): 85,1070 1405,1070 1405,230 85,230
GND on Top Layer "Top Layer-GND" (solid, shelved, pour order 8): 85,1070 1405,1070 1405,230 85,230

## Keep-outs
Bottom Layer:
  region: 0,350 450,350 450,522.14 487.5,565 640,565 640,515 555,515 555,225 0,225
